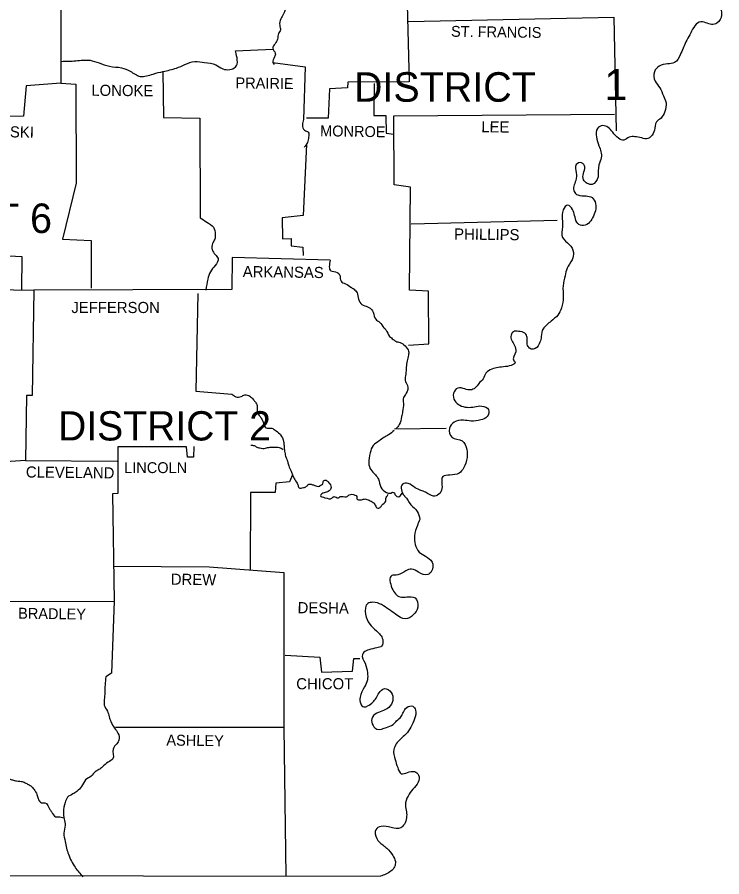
# Model space of a CAD drawing. Extents: x 21307 to 29830, y 1322443 to 1332359.
# Drawn here: x 25498.6 to 25770.9, y 1325967.7 to 1326299.6 of the extents above; entities that cross this region are included whole.
import ezdxf

# ---------------------------------------------------------------- set-up
doc = ezdxf.new("R2010")
doc.units = 0
doc.layers.add('R_Draft', color=7, linetype='Continuous')

msp = doc.modelspace()

# ---------------------------------------------------------------- linework, layer by layer
at = {"layer": 'R_Draft'}
msp.add_line((25644.46, 1326140.7), (25664.46, 1326141), dxfattribs=at)
for points in [[(25508.86, 1326502.6), (25509.06, 1326478.8), (25507.36, 1326478.7), (25507.66, 1326453.8), (25500.66, 1326452.8), (25501.26, 1326446.1), (25503.66, 1326443), (25503.46, 1326435.1), (25489.86, 1326434.6), (25489.36, 1326422.4), (25476.96, 1326422), (25476.36, 1326407.2), (25477.06, 1326406), (25477.36, 1326382.4), (25498.76, 1326381), (25498.46, 1326328.3), (25515.46, 1326327.8), (25515.46, 1326274.2), (25502.06, 1326273.2), (25501.06, 1326261.4), (25478.56, 1326261.3)], [(25648.66, 1326329.5), (25650.16, 1326274.7), (25626.36, 1326274.6), (25626.26, 1326272.4), (25619.36, 1326272), (25618.76, 1326260.6), (25610.36, 1326260.6)], [(25649.86, 1326298), (25729.26, 1326299.6)], [(25729.26, 1326299.6), (25730.06, 1326255.8)], [(25729.26, 1326299.6), (25730.06, 1326255.8)], [(25729.26, 1326299.6), (25730.06, 1326255.8)], [(25729.26, 1326299.6), (25730.06, 1326255.8)], [(25729.26, 1326299.6), (25730.06, 1326255.8)], [(25729.26, 1326299.6), (25730.06, 1326255.8)], [(25729.26, 1326299.6), (25730.06, 1326255.8)], [(25729.26, 1326299.6), (25730.06, 1326255.8)], [(25582.96, 1326286.6), (25597.46, 1326287.3)], [(25597.46, 1326282.1), (25609.96, 1326280.5), (25609.26, 1326260.1)], [(25554.96, 1326278.8), (25555.16, 1326260.9), (25569.26, 1326260.6), (25569.36, 1326222.2)], [(25515.46, 1326274.2), (25521.26, 1326273.8), (25521.36, 1326235.6), (25516.16, 1326213.9), (25527.26, 1326213.4), (25527.16, 1326195)], [(25636.56, 1326274.1), (25636.46, 1326261.7), (25641.06, 1326261.7), (25641.26, 1326254.8), (25644.16, 1326254.5)], [(25649.86, 1326173), (25657.66, 1326173.5), (25657.56, 1326193.8), (25650.26, 1326194.3), (25650.66, 1326234), (25644.36, 1326234.9), (25644.16, 1326261.6), (25729.46, 1326262.2)], [(25610.36, 1326250.5), (25609.16, 1326223.1), (25600.96, 1326222.2), (25601.16, 1326214.1), (25604.46, 1326214.2), (25604.56, 1326211.4), (25609.06, 1326210.9), (25609.16, 1326207.6)], [(25438.26, 1326249.2), (25449.46, 1326248.5), (25449.06, 1326236), (25462.16, 1326235.5), (25462.36, 1326224.6), (25468.56, 1326224.1), (25468.56, 1326222.2), (25474.36, 1326221.8), (25474.56, 1326214.8), (25487.76, 1326214.8), (25488.16, 1326207.9), (25500.36, 1326207.3), (25500.26, 1326194.3)], [(25650.86, 1326219.9), (25707.26, 1326221.3)], [(25619.56, 1326205.8), (25581.76, 1326206.8), (25581.56, 1326194.5), (25505.06, 1326194.2)], [(25447.46, 1326181), (25453.06, 1326181.8), (25453.46, 1326185.2), (25456.76, 1326185.8), (25456.96, 1326187.8), (25480.26, 1326188.5), (25481.16, 1326194.6), (25505.06, 1326194.2)], [(25505.06, 1326194.2), (25504.46, 1326153.6), (25502.16, 1326153.5), (25501.86, 1326128.4)], [(25568.46, 1326192.9), (25567.66, 1326155.2), (25581.56, 1326154.1)], [(25566.93, 1326133.86), (25566.76, 1326129.8), (25564.46, 1326129.8), (25564.06, 1326133.7), (25537.46, 1326133.7), (25537.49, 1326128.2)], [(25501.86, 1326128.4), (25488.03, 1326127.55)], [(25501.86, 1326128.4), (25537.26, 1326128.2)], [(25537.49, 1326128.2), (25537.56, 1326115.7), (25535.46, 1326115.6), (25536.06, 1326074.1)], [(25605.06, 1326122.9), (25603.86, 1326120.2), (25598.56, 1326119.7), (25598.26, 1326116.1), (25588.76, 1326116.1), (25588.66, 1326086.2)], [(25642.06, 1326115.8), (25642.96, 1326115.87), (25643.62, 1326116.17), (25644.38, 1326115.93), (25644.6, 1326115.28), (25645.33, 1326114.58), (25646.16, 1326114.48), (25646.76, 1326114.97), (25647.42, 1326115.8)], [(25535.76, 1326087.7), (25572.86, 1326087.4), (25601.66, 1326085.2)], [(25601.66, 1326085.2), (25601.66, 1326025.4), (25602.46, 1325967.9)], [(25490.86, 1326074), (25536.06, 1326074.1)], [(25536.06, 1326074.1), (25535.06, 1326046.3), (25532.86, 1326044.9)], [(25602.16, 1326053.3), (25615.56, 1326052.5), (25616.16, 1326046.7), (25628.26, 1326047.1), (25628.76, 1326052), (25631.06, 1326052)], [(25272.26, 1326049.4), (25272.46, 1325968.5), (25638.96, 1325967.9)], [(25536.66, 1326025.5), (25601.66, 1326025.5)]]:
    msp.add_lwpolyline(points, dxfattribs=at)
for points in [[(25610.16, 1326341.1), (25609.66, 1326337.8), (25607.76, 1326336.9), (25605.56, 1326334.7), (25605.06, 1326332.7), (25603.26, 1326331.9), (25601.56, 1326329.8), (25600.46, 1326326.9), (25600.46, 1326323.9), (25601.16, 1326320.5), (25603.66, 1326319.6), (25604.86, 1326317.6), (25604.66, 1326315.5), (25607.06, 1326314.1), (25607.46, 1326312.9), (25607.06, 1326311.6), (25605.96, 1326307.9), (25606.06, 1326305.4), (25605.86, 1326304.3), (25603.16, 1326303.6), (25601.56, 1326300.9), (25600.46, 1326299), (25600.06, 1326296.5), (25600.36, 1326294.7), (25599.56, 1326293.3), (25599.26, 1326291.2), (25598.26, 1326289.4), (25597.36, 1326287.7), (25598.36, 1326285.7), (25598.06, 1326284.3), (25597.46, 1326282.1), (25597.96, 1326281.4)], [(25766.56, 1326337.1), (25766.96, 1326334.2), (25765.26, 1326331.1), (25764.66, 1326328), (25764.96, 1326324.9), (25761.76, 1326323.2), (25758.96, 1326321.2), (25760.56, 1326318.8), (25763.56, 1326316.6), (25766.56, 1326314.9), (25768.46, 1326313.2), (25768.96, 1326309.1), (25769.46, 1326306.5), (25770.46, 1326302.9), (25770.86, 1326300.4), (25769.06, 1326297.4), (25766.96, 1326296.8), (25764.76, 1326297.5), (25762.16, 1326297.7), (25760.06, 1326295.7), (25758.56, 1326292.9), (25757.06, 1326290.1), (25755.96, 1326287.7), (25754.86, 1326285.1), (25752.66, 1326282.1), (25749.96, 1326281.6), (25746.76, 1326280.8), (25744.86, 1326278.6), (25745.16, 1326274.9), (25746.96, 1326272.4), (25748.36, 1326269.3), (25749.36, 1326266.6), (25748.86, 1326263.2), (25747.46, 1326260.7), (25745.66, 1326259.2), (25744.86, 1326256), (25743.56, 1326253.6), (25742.36, 1326252.8), (25739.96, 1326253), (25737.36, 1326253.5), (25735.16, 1326253.3), (25733.06, 1326252.2), (25730.96, 1326252.9), (25728.76, 1326255.3), (25726.96, 1326257.1), (25724.96, 1326257.8), (25722.86, 1326256.7), (25722.46, 1326253.4), (25723.46, 1326250), (25724.36, 1326245.4), (25723.46, 1326242.6), (25723.16, 1326238)], [(25515.66, 1326282.6), (25521.26, 1326282.8), (25526.76, 1326283), (25530.26, 1326282), (25534.26, 1326280.7), (25538.96, 1326280.1), (25542.26, 1326278.8), (25546.16, 1326276.8), (25551.16, 1326277.7), (25555.06, 1326278.7), (25560.16, 1326280), (25563.46, 1326281.4), (25567.26, 1326282.6), (25571.06, 1326282.1), (25575.36, 1326281.3), (25578.06, 1326279.7), (25582.96, 1326280.4), (25582.96, 1326286.6)], [(25609.26, 1326260.1), (25608.86, 1326258.1), (25609.66, 1326256), (25611.06, 1326255.3), (25611.26, 1326253.3), (25610.76, 1326251.3), (25610.36, 1326250.5), (25609.46, 1326249.3)], [(25723.16, 1326238), (25720.86, 1326235.1), (25717.46, 1326236.9), (25717.46, 1326239.3), (25717.96, 1326241.8), (25716.76, 1326243.4), (25714.66, 1326242.7), (25714.66, 1326239.6), (25714.46, 1326236.6), (25713.86, 1326232.3), (25715.26, 1326231), (25718.46, 1326230.6), (25720.76, 1326230), (25722.16, 1326227.7), (25722.06, 1326224.9), (25720.96, 1326222.2), (25719.36, 1326220), (25716.86, 1326219.2), (25714.86, 1326220.5), (25714.06, 1326223.1), (25713.16, 1326225.4), (25711.46, 1326227.1), (25709.66, 1326225.2), (25709.26, 1326221.7), (25709.36, 1326218.7), (25709.36, 1326214.6), (25711.96, 1326211.9), (25713.56, 1326208.8), (25713.06, 1326206), (25711.16, 1326202.7), (25710.36, 1326199.8), (25709.56, 1326195.9), (25709.66, 1326191.6), (25708.96, 1326187.4), (25707.56, 1326184.6), (25704.96, 1326182.3), (25703.26, 1326180.8), (25701.86, 1326179.3), (25701.16, 1326176.3), (25700.66, 1326174.2), (25698.76, 1326171.7), (25697.26, 1326171.5), (25696.06, 1326172.5), (25695.66, 1326174.2), (25695.66, 1326175.9), (25694.86, 1326177.6), (25692.36, 1326178.3), (25690.36, 1326178.2), (25689.46, 1326176.8), (25690.76, 1326172.9), (25691.26, 1326170.4), (25690.56, 1326167), (25690.96, 1326166.6), (25687.36, 1326164.7), (25684.46, 1326164.4), (25682.06, 1326163.7), (25679.76, 1326162.2), (25678.66, 1326160), (25677.06, 1326158.2), (25675.66, 1326156.5), (25673.76, 1326155.7), (25671.66, 1326156.1), (25668.86, 1326156.4), (25667.26, 1326154.4), (25667.76, 1326151.5), (25669.66, 1326149.8), (25672.46, 1326149), (25675.36, 1326149.2), (25678.16, 1326149.5), (25680.76, 1326148.1), (25680.26, 1326145.4), (25677.76, 1326144.1), (25674.06, 1326143.7), (25671.06, 1326144), (25667.46, 1326143.2), (25665.66, 1326140.9), (25666.66, 1326137.4), (25670.56, 1326136), (25672.36, 1326132.7), (25672.46, 1326129.6), (25671.16, 1326125.5), (25669.36, 1326123.6), (25665.86, 1326122.8), (25663.16, 1326122.3), (25662.76, 1326117.7), (25661.56, 1326115.4), (25659.46, 1326114.7), (25656.46, 1326116.2), (25654.66, 1326116.9), (25652.46, 1326117.9), (25649.66, 1326119.6), (25647.56, 1326119.3), (25648.16, 1326114.9), (25648.36, 1326114.7), (25650.76, 1326111.4), (25653.16, 1326108.8), (25654.26, 1326105.7)], [(25569.36, 1326222.2), (25571.86, 1326220.5), (25574.46, 1326218.5), (25575.16, 1326215.8), (25574.96, 1326213.9), (25574.16, 1326212.3), (25573.96, 1326209.8), (25575.16, 1326208), (25576.26, 1326206.5), (25575.16, 1326203.8), (25573.26, 1326201.3), (25572.26, 1326198.5), (25571.56, 1326194.3)], [(25619.56, 1326205.8), (25619.86, 1326201.7), (25622.26, 1326201.1), (25623.26, 1326200), (25623.76, 1326197.7), (25625.46, 1326196.7), (25627.76, 1326195.3), (25629.16, 1326194.3), (25630.16, 1326192.7), (25630.76, 1326190.1), (25632.36, 1326188.4), (25634.56, 1326187.6), (25636.16, 1326185.7), (25637.16, 1326183), (25638.76, 1326181.8), (25640.36, 1326179.7), (25641.16, 1326178.8), (25642.56, 1326176.4), (25643.96, 1326175.2), (25644.96, 1326174.5), (25646.56, 1326174), (25648.56, 1326172.7), (25649.86, 1326170.7), (25649.86, 1326169.2), (25649.36, 1326166.9), (25648.96, 1326164.5), (25648.76, 1326161.8), (25648.56, 1326159.4), (25649.46, 1326157.4), (25648.96, 1326154.4), (25647.96, 1326152.8), (25647.86, 1326150.6), (25647.56, 1326147.3), (25647.16, 1326145.4), (25646.26, 1326142.3), (25644.96, 1326140.7)], [(25581.56, 1326154.1), (25583.06, 1326153.1), (25585.16, 1326153.2), (25586.56, 1326153.8), (25587.66, 1326153.7), (25589.16, 1326152.8), (25590.16, 1326151.6), (25590.86, 1326150.7), (25591.36, 1326149.3), (25591.36, 1326148), (25591.86, 1326146.2), (25592.46, 1326145.5), (25593.26, 1326144.2), (25593.76, 1326143), (25594.06, 1326142.2), (25595.16, 1326140.9), (25596.16, 1326141), (25597.06, 1326140.9), (25598.26, 1326140.2), (25600.06, 1326138.8), (25600.36, 1326138.4), (25601.56, 1326135.8), (25601.76, 1326134.2), (25601.96, 1326132.1), (25602.36, 1326130.1), (25603.16, 1326127.9), (25603.56, 1326126.4), (25604.46, 1326124.3), (25605.06, 1326122.9), (25605.86, 1326121.1), (25607.06, 1326119.1), (25607.56, 1326117.9), (25609.26, 1326118), (25610.46, 1326118.5), (25611.36, 1326119.3), (25612.46, 1326119.2), (25613.66, 1326118.8), (25615.26, 1326118.5), (25616.26, 1326119.1), (25616.76, 1326119.5), (25616.86, 1326120.4), (25617.76, 1326120.9), (25618.76, 1326120.2), (25619.86, 1326118.6), (25619.86, 1326117.6), (25619.46, 1326117), (25618.16, 1326116.2), (25616.36, 1326115.6), (25615.86, 1326114.9), (25617.56, 1326114.1), (25620.26, 1326113.9), (25620.96, 1326114.5), (25622.76, 1326114), (25623.46, 1326114.5), (25625.86, 1326114.4), (25626.96, 1326115.2), (25629.16, 1326115.1), (25629.86, 1326114.6), (25629.86, 1326113.7), (25631.66, 1326113.3), (25632.96, 1326113.6), (25634.66, 1326113.1), (25636.16, 1326112.3), (25636.96, 1326111.2), (25637.96, 1326110), (25638.86, 1326110.3), (25639.56, 1326111.2), (25641.06, 1326112.8), (25641.06, 1326113.8), (25641.46, 1326114.5), (25641.96, 1326115.5)], [(25644.26, 1326140.1), (25642.16, 1326138.4), (25640.36, 1326137.4), (25638.46, 1326136), (25636.16, 1326134.3), (25635.06, 1326131.4), (25634.46, 1326127.4), (25635.26, 1326125), (25637.06, 1326122.9), (25638.26, 1326121.2), (25639.16, 1326118.2), (25641.36, 1326116.1), (25642.06, 1326115.8)], [(25588.96, 1326134.41), (25589.16, 1326134.4), (25590.46, 1326134.1), (25591.56, 1326133.5), (25592.36, 1326133.3), (25593.56, 1326133.1), (25594.56, 1326133.2), (25596.26, 1326133.6), (25597.26, 1326133.6), (25598.86, 1326133.6), (25599.86, 1326133.5), (25601.36, 1326132.7)], [(25654.26, 1326105.7), (25653.26, 1326103.4), (25652.16, 1326099.4), (25652.46, 1326096), (25653.96, 1326093.1), (25656.36, 1326091.5), (25658.96, 1326089.2), (25658.76, 1326085.7), (25657.26, 1326084.4), (25653.76, 1326085.3), (25651.06, 1326086.5), (25648.76, 1326085.8), (25645.66, 1326084.3), (25643.36, 1326084), (25643.46, 1326079.2), (25646.56, 1326075.8), (25649.26, 1326075.8), (25652.36, 1326075.4), (25653.46, 1326071.8), (25651.66, 1326068.8), (25648.66, 1326067.3), (25644.86, 1326069.1), (25642.16, 1326071), (25639.46, 1326072.8), (25636.06, 1326073.7), (25634.16, 1326073.3), (25633.26, 1326069.1), (25634.86, 1326065.3), (25637.46, 1326062.7), (25639.86, 1326059.3), (25639.46, 1326056.8), (25637.66, 1326056.1), (25634.46, 1326055.4), (25632.56, 1326054.4), (25632.06, 1326053.6), (25633.06, 1326050.2), (25633.96, 1326046.5), (25633.96, 1326043.7), (25632.86, 1326041.1), (25631.16, 1326037.1), (25631.36, 1326034.5), (25632.56, 1326033.3), (25634.06, 1326033.7), (25636.06, 1326035.1), (25637.36, 1326036.7), (25638.46, 1326038.7), (25640.56, 1326040.4), (25643.16, 1326038.9), (25643.76, 1326035.8), (25642.26, 1326033.1), (25640.16, 1326031.9), (25637.56, 1326030.9), (25635.66, 1326028.7), (25636.16, 1326026.1), (25637.66, 1326024.7), (25641.36, 1326025.4), (25643.86, 1326026.5), (25645.26, 1326027.9), (25646.96, 1326029.6), (25647.86, 1326031.3), (25649.16, 1326033.1), (25651.46, 1326033.6), (25652.56, 1326032.1), (25652.16, 1326028.7), (25650.76, 1326025.5), (25648.86, 1326022.8), (25646.76, 1326020.9), (25644.16, 1326016.8), (25644.66, 1326013), (25645.66, 1326009.9), (25647.06, 1326007.5), (25649.46, 1326008), (25652.16, 1326008.3), (25653.76, 1326007), (25653.56, 1326004.2), (25651.56, 1326001.5), (25649.66, 1325998.9), (25648.66, 1325995.3), (25649.06, 1325992.8), (25649.06, 1325990.5), (25648.26, 1325988), (25646.86, 1325986.6), (25643.16, 1325986.7), (25639.26, 1325987.1), (25637.16, 1325985.9), (25637.56, 1325982.5), (25639.86, 1325980), (25641.46, 1325978.7), (25643.76, 1325975.9), (25644.76, 1325973.6), (25644.46, 1325971.6), (25643.06, 1325969.9), (25638.96, 1325967.9)], [(25532.86, 1326044.9), (25532.56, 1326041.8), (25532.46, 1326038.9), (25532.26, 1326036.1), (25532.26, 1326034), (25533.46, 1326031.7), (25534.16, 1326029.5), (25534.86, 1326027.6), (25536.26, 1326025.1), (25537.56, 1326023.2), (25537.96, 1326020.5), (25537.16, 1326019.1), (25535.66, 1326017), (25535.56, 1326013.2), (25533.76, 1326012), (25531.46, 1326010), (25530.16, 1326009.1), (25528.76, 1326008.2), (25527.26, 1326006.6), (25525.06, 1326005.1), (25523.46, 1326002.6), (25521.66, 1326000.7), (25520.16, 1325999.7), (25518.06, 1325998.4), (25517.16, 1325996.4), (25516.46, 1325992.7), (25516.76, 1325990), (25517.16, 1325987.6), (25516.66, 1325984.6), (25517.16, 1325981.3), (25517.66, 1325978.7), (25518.46, 1325976.4), (25519.56, 1325973.8), (25520.96, 1325971.4), (25523.96, 1325967.7)], [(25433.16, 1326021.8), (25434.76, 1326022.9), (25436.26, 1326023.5), (25437.76, 1326023.2), (25439.36, 1326023), (25440.76, 1326023.2), (25442.56, 1326022.9), (25444.06, 1326022), (25445.76, 1326021.3), (25447.46, 1326021.3), (25448.96, 1326021.3), (25450.26, 1326020.4), (25452.66, 1326020.5), (25454.66, 1326021.3), (25456.66, 1326021.9), (25459.36, 1326022.2), (25461.76, 1326020.5), (25463.46, 1326019.1), (25464.86, 1326017.5), (25465.86, 1326015.7), (25466.96, 1326014.7), (25468.76, 1326014), (25470.16, 1326013.7), (25471.86, 1326013.2), (25472.76, 1326012.8), (25473.56, 1326010.9), (25474.86, 1326008.3), (25477.36, 1326007.4), (25480.46, 1326008.6), (25482.96, 1326009.3), (25484.76, 1326009.9), (25485.86, 1326010.3), (25486.86, 1326010.4), (25486.56, 1326010.6), (25487.76, 1326010.9), (25488.86, 1326010.1), (25489.56, 1326009), (25490.76, 1326007.4), (25491.86, 1326006), (25492.96, 1326005.5), (25494.06, 1326006.1), (25495.56, 1326005.6), (25496.86, 1326005.1), (25498.36, 1326004.7), (25499.66, 1326004.6), (25501.36, 1326004.2), (25502.66, 1326003.5), (25503.86, 1326002.8), (25505.06, 1326001.5), (25506.26, 1325999.5), (25506.66, 1325997.9), (25508.06, 1325996.3), (25509.36, 1325996.3), (25511.26, 1325993.7), (25511.96, 1325992.7), (25513.46, 1325990.9), (25514.56, 1325990.9), (25516.66, 1325990.5)]]:
    msp.add_spline(points, degree=3, dxfattribs=at)

# ---------------------------------------------------------------- texts
for s, height, rotation, p in [('ST. FRANCIS', 4.1993, 359.2216, (25666.26, 1326292.1)), ('PRAIRIE', 4.2, 359.2116, (25582.96, 1326272.2)), ('LONOKE', 4.301, 359.4974, (25527.26, 1326269.3)), ('PULASKI', 4.301, 359.053, (25480.76, 1326253.5)), ('MONROE', 4.199, 359.0331, (25615.66, 1326253.7)), ('LEE', 4.301, 359.4327, (25677.96, 1326255.2)), ('PHILLIPS', 4.3, 359.3179, (25667.46, 1326213.8)), ('ARKANSAS', 4.3, 359.2678, (25585.76, 1326199.3)), ('CLEVELAND', 4.301, 359.3376, (25501.96, 1326121.9)), ('DREW', 4.299, 359.2258, (25557.96, 1326080.5)), ('BRADLEY', 4.199, 359.1449, (25498.96, 1326067.4)), ('DESHA', 4.299, 359.3704, (25606.96, 1326069.5)), ('ASHLEY', 4.201, 359.2361, (25556.26, 1326018.4))]:
    msp.add_text(s, height=height, rotation=rotation, dxfattribs=at).set_placement(p)
for s, height, p in [('1', 12, (25725.56, 1326267.7)), ('DISTRICT', 11.4, (25628.76, 1326267)), ('DISTRICT 6', 11.4, (25429.06, 1326216.3)), ('JEFFERSON', 4.3, (25519.56, 1326185.4)), ('DISTRICT 2', 11.3, (25514.4, 1326136.19)), ('LINCOLN', 4.2, (25539.96, 1326123.6)), ('CHICOT', 4.3, (25606.46, 1326040.1))]:
    msp.add_text(s, height=height, dxfattribs=at).set_placement(p)

doc.saveas('drawing.dxf')
